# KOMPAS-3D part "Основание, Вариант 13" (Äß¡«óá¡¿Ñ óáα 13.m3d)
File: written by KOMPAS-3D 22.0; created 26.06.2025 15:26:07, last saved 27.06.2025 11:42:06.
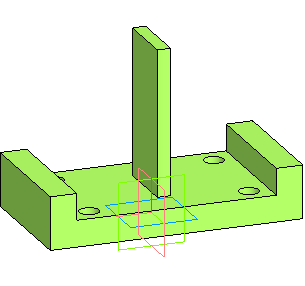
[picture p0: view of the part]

Document properties: Автор: Helen; Полное имя файла: D:\MY\WORK\MPEI\ППЭ_2025-2026\Варианты\Вар 13 СБ\Основание вар 13.m3d

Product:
- Part/product: Основание  | designation Вариант 13
    Масса: 3.93188

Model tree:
1. Эскиз:1
2. Элемент выдавливания:1
     Расстояние 1 = 20
3. Эскиз:3  (with: Элемент выдавливания:1)
4. Элемент выдавливания:3
     Расстояние 2 = 20
5. Массив по сетке:1  (with: Элемент выдавливания:3, Эскиз:3, Элемент выдавливания:1)  (4 pattern instances)
     Шаг 1 = 120; Угол раствора = 90; Шаг 2 = 70
6. Эскиз:4  (with: Элемент выдавливания:1)
7. Элемент выдавливания:4
     Расстояние 1 = 20
8. Зеркальный массив:1
9. Экземпляр ( 1 )
10. Экземпляр ( 2 )  (with: Элемент выдавливания:4)
11. Эскиз:5  (with: Элемент выдавливания:1)
12. Элемент выдавливания:5
     Расстояние 1 = 110

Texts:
  Вариант 13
